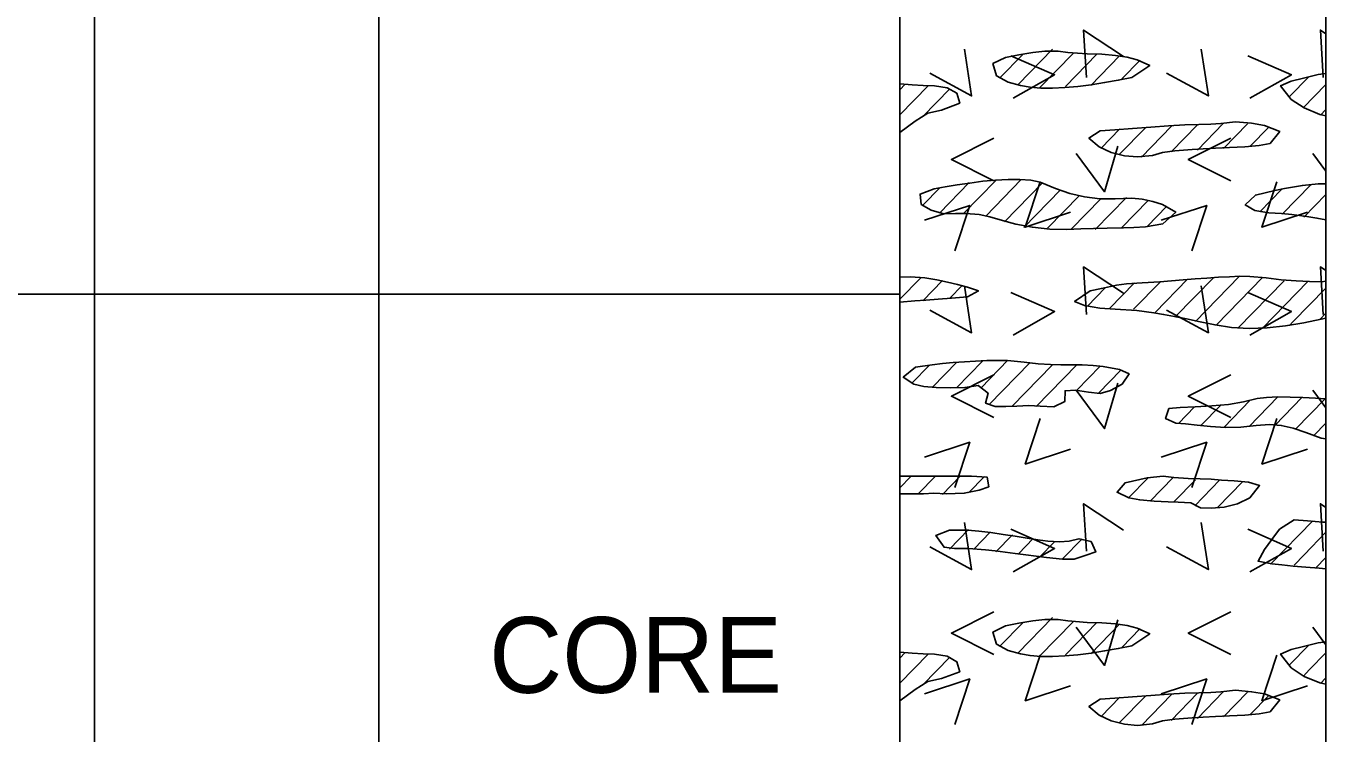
# Model space of a CAD drawing. Extents: x 0 to 0.833, y -0.323 to 0.608.
# Drawn here: x 0.719 to 0.8333, y -0.2609 to -0.1987 of the extents above; entities that cross this region are included whole.
import ezdxf

# ---------------------------------------------------------------- set-up
doc = ezdxf.new("R2010")
doc.units = 0

msp = doc.modelspace()

# ---------------------------------------------------------------- linework, layer by layer
for points in [[(0, -0.32328), (0.83333, -0.32328), (0.83333, 0.60833), (0, 0.60833)], [(0.81233, -0.20113), (0.81063, -0.20101), (0.80977, -0.20088), (0.8086, -0.20087), (0.80755, -0.20101), (0.80632, -0.20121), (0.80513, -0.20145), (0.80403, -0.20198), (0.80436, -0.20304), (0.80536, -0.2036), (0.80647, -0.2039), (0.8073, -0.20405), (0.80824, -0.20413), (0.80926, -0.20414), (0.81035, -0.20409), (0.81149, -0.20398), (0.81267, -0.20384), (0.81386, -0.20365), (0.81506, -0.20344), (0.81625, -0.20321), (0.81783, -0.20213), (0.81673, -0.20163), (0.81585, -0.20142), (0.8148, -0.20127), (0.81361, -0.20116)], [(0.83265, -0.20294), (0.83136, -0.20325), (0.83028, -0.20352), (0.82934, -0.20392), (0.83026, -0.20512), (0.83142, -0.20588), (0.83279, -0.20646), (0.83333, -0.20656), (0.83333, -0.20285)], [(0.79583, -0.20804), (0.79719, -0.20705), (0.79831, -0.20635), (0.79951, -0.20607), (0.80111, -0.20547), (0.80086, -0.20459), (0.80002, -0.20411), (0.79889, -0.20392), (0.79791, -0.20389), (0.79694, -0.20383), (0.79583, -0.20375)], [(0.82537, -0.20709), (0.82408, -0.20724), (0.82319, -0.2073), (0.82214, -0.20732), (0.82091, -0.20736), (0.81947, -0.20745), (0.81792, -0.20757), (0.81632, -0.20769), (0.81475, -0.20779), (0.81348, -0.20789), (0.81247, -0.20853), (0.81337, -0.20929), (0.81444, -0.20979), (0.81561, -0.21008), (0.81675, -0.21019), (0.81807, -0.21007), (0.81896, -0.2098), (0.82003, -0.20965), (0.82157, -0.20953), (0.82253, -0.20947), (0.82362, -0.20942), (0.82483, -0.20935), (0.82618, -0.20929), (0.82745, -0.20918), (0.82842, -0.209), (0.82927, -0.20795), (0.82791, -0.20743), (0.82679, -0.20723)], [(0.79885, -0.213), (0.79763, -0.21346), (0.79773, -0.21436), (0.79859, -0.21488), (0.7997, -0.21518), (0.80074, -0.21517), (0.80165, -0.21515), (0.80281, -0.21524), (0.80377, -0.21545), (0.80486, -0.21579), (0.80606, -0.21609), (0.80751, -0.21637), (0.80905, -0.21655), (0.81052, -0.21658), (0.81177, -0.21652), (0.81289, -0.21648), (0.81408, -0.21645), (0.81553, -0.21641), (0.81642, -0.21638), (0.81745, -0.21635), (0.81897, -0.21608), (0.82011, -0.21504), (0.81896, -0.21437), (0.8181, -0.21411), (0.81717, -0.21391), (0.81626, -0.2138), (0.81479, -0.21386), (0.81343, -0.21386), (0.8121, -0.21371), (0.8108, -0.21341), (0.80953, -0.21295), (0.8082, -0.2124), (0.80736, -0.21224), (0.8064, -0.21216), (0.80536, -0.21216), (0.80427, -0.21222), (0.80314, -0.21233), (0.80201, -0.21248), (0.8009, -0.21264), (0.79984, -0.21282)], [(0.83263, -0.21256), (0.83126, -0.21269), (0.82969, -0.21296), (0.82883, -0.21313), (0.82712, -0.21354), (0.82623, -0.21441), (0.82708, -0.2149), (0.82831, -0.21509), (0.82941, -0.21516), (0.83033, -0.21524), (0.83165, -0.21543), (0.83253, -0.21557), (0.83333, -0.21571), (0.83333, -0.21256)], [(0.82816, -0.22521), (0.82978, -0.22504), (0.83137, -0.22479), (0.8329, -0.22447), (0.83333, -0.22437), (0.83333, -0.22113), (0.83295, -0.22116), (0.83188, -0.22114), (0.83071, -0.22109), (0.82938, -0.22099), (0.82807, -0.22082), (0.82662, -0.2207), (0.82576, -0.22069), (0.82484, -0.22072), (0.82387, -0.22077), (0.82286, -0.22084), (0.82182, -0.22092), (0.82077, -0.221), (0.81973, -0.22109), (0.81872, -0.22116), (0.81715, -0.22126), (0.81579, -0.22135), (0.81491, -0.22148), (0.81357, -0.22176), (0.8126, -0.22197), (0.81121, -0.22289), (0.8121, -0.22325), (0.81345, -0.2235), (0.81479, -0.22359), (0.81668, -0.22369), (0.81818, -0.22389), (0.81905, -0.22404), (0.82, -0.22422), (0.82107, -0.22443), (0.82225, -0.22468), (0.82357, -0.22497), (0.82501, -0.2252), (0.82656, -0.22527)], [(0.79583, -0.22296), (0.79715, -0.22285), (0.79814, -0.22278), (0.79922, -0.2227), (0.80039, -0.22261), (0.80179, -0.22249), (0.80275, -0.22198), (0.80179, -0.22163), (0.80091, -0.22142), (0.80003, -0.2212), (0.79909, -0.22099), (0.79803, -0.22083), (0.79677, -0.22073), (0.79583, -0.22075)], [(0.79708, -0.23019), (0.79794, -0.23037), (0.79904, -0.23048), (0.80028, -0.23051), (0.80156, -0.23046), (0.80274, -0.2303), (0.80361, -0.23097), (0.80338, -0.23186), (0.80422, -0.23213), (0.80517, -0.23215), (0.80613, -0.2321), (0.8072, -0.23206), (0.80818, -0.2321), (0.80939, -0.23217), (0.81037, -0.2317), (0.81038, -0.23076), (0.8113, -0.23069), (0.81244, -0.23088), (0.81346, -0.23099), (0.81438, -0.23073), (0.81539, -0.23019), (0.81601, -0.22928), (0.81517, -0.2289), (0.81374, -0.22863), (0.81285, -0.22853), (0.81187, -0.22848), (0.81, -0.22847), (0.8091, -0.22846), (0.808, -0.22838), (0.80678, -0.22823), (0.8053, -0.2281), (0.80443, -0.22808), (0.80349, -0.2281), (0.80251, -0.22814), (0.80152, -0.2282), (0.80054, -0.22828), (0.79959, -0.22837), (0.7987, -0.22847), (0.79722, -0.22869), (0.79614, -0.22957)], [(0.83241, -0.23141), (0.83129, -0.23134), (0.83017, -0.23131), (0.8291, -0.2313), (0.82811, -0.23134), (0.82728, -0.23143), (0.82608, -0.23173), (0.82476, -0.23196), (0.8233, -0.23209), (0.82183, -0.23218), (0.82051, -0.23224), (0.81951, -0.23233), (0.81922, -0.2332), (0.82013, -0.23362), (0.82097, -0.23367), (0.822, -0.23377), (0.82318, -0.2339), (0.82448, -0.23399), (0.82584, -0.23396), (0.82719, -0.2338), (0.82836, -0.23373), (0.8294, -0.23381), (0.83043, -0.23404), (0.83156, -0.23444), (0.83291, -0.23493), (0.83333, -0.235), (0.83333, -0.23148)], [(0.79583, -0.23982), (0.79676, -0.23983), (0.79792, -0.23981), (0.79882, -0.23977), (0.79992, -0.23982), (0.80151, -0.23977), (0.80282, -0.23951), (0.80367, -0.2392), (0.80354, -0.23836), (0.80216, -0.23827), (0.79583, -0.23827)], [(0.81822, -0.24047), (0.81944, -0.24052), (0.82033, -0.24056), (0.82145, -0.24063), (0.82229, -0.24105), (0.82324, -0.24109), (0.82438, -0.24099), (0.82555, -0.2407), (0.82662, -0.24019), (0.82749, -0.2391), (0.82651, -0.23879), (0.82524, -0.23869), (0.82413, -0.23863), (0.82324, -0.23852), (0.82226, -0.2385), (0.82121, -0.23848), (0.81995, -0.23839), (0.81902, -0.23827), (0.81761, -0.23841), (0.81566, -0.23885), (0.81496, -0.23969), (0.81598, -0.24018), (0.81695, -0.24036)], [(0.83305, -0.24232), (0.83171, -0.24221), (0.83054, -0.24211), (0.82925, -0.24293), (0.82857, -0.24384), (0.82792, -0.24473), (0.82735, -0.24575), (0.82858, -0.24598), (0.82945, -0.24608), (0.83045, -0.24618), (0.83155, -0.24627), (0.83272, -0.24637), (0.83333, -0.24642), (0.83333, -0.24233)], [(0.80066, -0.24462), (0.80188, -0.24463), (0.80339, -0.24476), (0.80423, -0.24485), (0.8051, -0.24496), (0.806, -0.24508), (0.80692, -0.2452), (0.80784, -0.24532), (0.80875, -0.24543), (0.81014, -0.24557), (0.81119, -0.24556), (0.81222, -0.24522), (0.81308, -0.24493), (0.81267, -0.24403), (0.8116, -0.24378), (0.81075, -0.24398), (0.80989, -0.24406), (0.80885, -0.24398), (0.80799, -0.24387), (0.80703, -0.24373), (0.806, -0.24356), (0.80492, -0.2434), (0.80384, -0.24324), (0.8028, -0.24311), (0.80182, -0.24301), (0.8002, -0.24301), (0.79901, -0.24348), (0.79974, -0.24452)], [(0.81233, -0.25113), (0.81063, -0.25101), (0.80977, -0.25088), (0.8086, -0.25087), (0.80755, -0.25101), (0.80632, -0.25121), (0.80513, -0.25145), (0.80403, -0.25198), (0.80436, -0.25304), (0.80536, -0.2536), (0.80647, -0.2539), (0.8073, -0.25405), (0.80824, -0.25413), (0.80926, -0.25414), (0.81035, -0.25409), (0.81149, -0.25398), (0.81267, -0.25384), (0.81386, -0.25365), (0.81506, -0.25344), (0.81625, -0.25321), (0.81783, -0.25213), (0.81673, -0.25163), (0.81585, -0.25142), (0.8148, -0.25127), (0.81361, -0.25116)], [(0.79583, -0.25804), (0.79719, -0.25705), (0.79831, -0.25634), (0.79951, -0.25607), (0.80111, -0.25547), (0.80086, -0.25459), (0.80002, -0.25411), (0.79889, -0.25392), (0.79791, -0.25389), (0.79694, -0.25383), (0.79583, -0.25375)], [(0.83265, -0.25294), (0.83136, -0.25325), (0.83028, -0.25352), (0.82934, -0.25392), (0.83026, -0.25512), (0.83142, -0.25588), (0.83279, -0.25646), (0.83333, -0.25656), (0.83333, -0.25285)], [(0.82537, -0.25709), (0.82408, -0.25724), (0.82319, -0.2573), (0.82214, -0.25732), (0.82091, -0.25736), (0.81947, -0.25745), (0.81792, -0.25757), (0.81632, -0.25769), (0.81475, -0.25779), (0.81348, -0.25789), (0.81247, -0.25853), (0.81337, -0.25929), (0.81444, -0.25979), (0.81561, -0.26008), (0.81675, -0.26019), (0.81807, -0.26007), (0.81896, -0.2598), (0.82003, -0.25965), (0.82157, -0.25953), (0.82253, -0.25947), (0.82362, -0.25942), (0.82483, -0.25935), (0.82618, -0.25929), (0.82745, -0.25918), (0.82842, -0.259), (0.82927, -0.25795), (0.82791, -0.25743), (0.82679, -0.25723)]]:
    msp.add_lwpolyline(points, close=True)
for points in [[(0.725, 0.55417), (0.725, -0.28575)], [(0.75, 0.55417), (0.75, -0.28575)], [(0.75, 0.55417), (0.75, -0.28575)], [(0.79583, 0.55417), (0.79583, -0.28575)], [(0.725, 0.54167), (0.725, -0.28575)], [(0.83333, -0.28575), (0.83333, 0.50165)], [(0.81551, -0.20134), (0.81201, -0.19903), (0.81226, -0.20321)], [(0.83333, -0.19935), (0.83284, -0.19903), (0.83309, -0.20321)], [(0.79847, -0.20282), (0.80215, -0.20482), (0.80153, -0.2007)], [(0.80465, -0.20324), (0.80667, -0.20117)], [(0.80626, -0.20381), (0.80928, -0.20071)], [(0.80809, -0.20414), (0.81111, -0.20105)], [(0.81041, -0.20398), (0.81318, -0.20115)], [(0.8193, -0.20282), (0.82299, -0.20482), (0.82236, -0.2007)], [(0.80562, -0.20128), (0.80946, -0.20296), (0.80581, -0.20502)], [(0.81264, -0.2039), (0.81518, -0.2013)], [(0.81536, -0.20333), (0.81699, -0.20167)], [(0.82645, -0.20128), (0.83029, -0.20296), (0.82664, -0.20502)], [(0.8301, -0.20491), (0.83184, -0.20312)], [(0.7963, -0.20379), (0.79583, -0.20427)], [(0.79834, -0.20392), (0.79583, -0.20649)], [(0.79786, -0.20662), (0.80023, -0.20419)], [(0.83131, -0.20588), (0.83333, -0.20381)], [(0.83285, -0.20651), (0.83333, -0.20602)], [(0.81519, -0.20772), (0.81354, -0.20942)], [(0.81514, -0.20998), (0.81748, -0.20759)], [(0.81709, -0.2102), (0.81974, -0.20749)], [(0.8197, -0.20975), (0.82203, -0.20735)], [(0.82202, -0.20958), (0.8243, -0.20725)], [(0.82431, -0.20945), (0.82644, -0.20726)], [(0.82663, -0.20928), (0.82834, -0.20753)], [(0.80412, -0.20853), (0.80038, -0.21041), (0.80412, -0.21228)], [(0.81134, -0.20988), (0.81384, -0.21325), (0.81503, -0.20925)], [(0.82496, -0.20853), (0.82121, -0.21041), (0.82496, -0.21228)], [(0.83217, -0.20988), (0.83333, -0.21144)], [(0, -0.21078), (0, -0.32328), (0.83333, -0.32328), (0.83333, -0.21078)], [(0.79933, -0.21513), (0.80195, -0.21244)], [(0.80142, -0.2152), (0.8043, -0.21225)], [(0.80653, -0.21217), (0.8034, -0.21539)], [(0.80506, -0.21589), (0.8084, -0.21247)], [(0.80818, -0.21237), (0.80687, -0.21637), (0.81087, -0.21505)], [(0.82901, -0.21237), (0.8277, -0.21637), (0.8317, -0.21505)], [(0.83203, -0.21261), (0.82949, -0.21521)], [(0.79938, -0.21287), (0.79786, -0.21442)], [(0.80997, -0.21307), (0.80675, -0.21638)], [(0.81164, -0.21358), (0.80884, -0.21644)], [(0.81303, -0.21658), (0.81579, -0.21375)], [(0.82751, -0.21502), (0.82945, -0.21303)], [(0.83138, -0.21548), (0.83333, -0.21348)], [(0.80069, -0.21845), (0.802, -0.21445), (0.798, -0.21576)], [(0.81353, -0.21386), (0.81094, -0.21651)], [(0.81534, -0.21642), (0.81768, -0.21402)], [(0.8176, -0.21632), (0.81934, -0.21453)], [(0.82152, -0.21845), (0.82284, -0.21445), (0.81884, -0.21576)], [(0.83333, -0.2157), (0.83333, -0.21569)], [(0.81551, -0.22217), (0.81201, -0.21986), (0.81226, -0.22405)], [(0.82569, -0.2207), (0.82184, -0.22465)], [(0.83333, -0.22018), (0.83284, -0.21986), (0.83309, -0.22405)], [(0.79765, -0.22085), (0.79583, -0.22271)], [(0.7996, -0.22106), (0.79786, -0.22284)], [(0.79847, -0.22366), (0.80215, -0.22566), (0.80153, -0.22153)], [(0.8013, -0.22154), (0.80027, -0.22259)], [(0.81392, -0.2217), (0.81235, -0.22331)], [(0.8143, -0.22352), (0.8165, -0.22127)], [(0.8164, -0.22359), (0.81879, -0.22114)], [(0.81829, -0.22387), (0.82114, -0.22094)], [(0.8193, -0.22366), (0.82299, -0.22566), (0.82236, -0.22153)], [(0.82004, -0.22429), (0.82346, -0.22078)], [(0.82775, -0.2208), (0.8237, -0.22495)], [(0.82964, -0.22108), (0.82557, -0.22526)], [(0.83173, -0.22115), (0.82774, -0.22524)], [(0.83333, -0.22173), (0.83042, -0.2247), (0.83012, -0.22502)], [(0.70417, -0.22225), (0.725, -0.22225)], [(0.725, -0.22225), (0.75, -0.22225)], [(0.75, -0.22225), (0.79583, -0.22225)], [(0.80562, -0.22211), (0.80946, -0.22379), (0.80581, -0.22586)], [(0.82645, -0.22211), (0.83029, -0.22379), (0.82664, -0.22586)], [(0.83281, -0.22447), (0.83333, -0.22394)], [(0.79844, -0.22851), (0.79691, -0.23008)], [(0.79871, -0.23045), (0.80085, -0.22825)], [(0.80083, -0.23049), (0.80311, -0.22815)], [(0.80534, -0.22807), (0.80299, -0.23049)], [(0.80367, -0.232), (0.80732, -0.22826)], [(0.80571, -0.23212), (0.80924, -0.22851)], [(0.81142, -0.22849), (0.80785, -0.23214)], [(0.81141, -0.23071), (0.81348, -0.22859)], [(0.80412, -0.22937), (0.80038, -0.23124), (0.80412, -0.23312)], [(0.81528, -0.22895), (0.81331, -0.23097)], [(0.82496, -0.22937), (0.82121, -0.23124), (0.82496, -0.23312)], [(0.81134, -0.23071), (0.81384, -0.23408), (0.81503, -0.23008)], [(0.83217, -0.23071), (0.83333, -0.23227)], [(0.82233, -0.23381), (0.82408, -0.23202)], [(0.82433, -0.23398), (0.82666, -0.23159)], [(0.82909, -0.2313), (0.82656, -0.2339)], [(0.82885, -0.23377), (0.83122, -0.23134)], [(0.83325, -0.23148), (0.83065, -0.23413)], [(0.80818, -0.2332), (0.80687, -0.2372), (0.81087, -0.23589)], [(0.82035, -0.23363), (0.82176, -0.23218)], [(0.82901, -0.2332), (0.8277, -0.2372), (0.8317, -0.23589)], [(0.83333, -0.2336), (0.83227, -0.23469)], [(0.80069, -0.23928), (0.802, -0.23528), (0.798, -0.23659)], [(0.82152, -0.23928), (0.82284, -0.23528), (0.81884, -0.23659)], [(0.79583, -0.2393), (0.79681, -0.2383)], [(0.79898, -0.23828), (0.79747, -0.23983)], [(0.80116, -0.23827), (0.79959, -0.23987)], [(0.80328, -0.23831), (0.80188, -0.23974)], [(0.8177, -0.23841), (0.81596, -0.24019)], [(0.81988, -0.23839), (0.81785, -0.24047)], [(0.82185, -0.23858), (0.81997, -0.24051)], [(0.824, -0.23859), (0.82178, -0.24087)], [(0.82601, -0.23875), (0.82378, -0.24103)], [(0.81551, -0.24301), (0.81201, -0.24069), (0.81226, -0.24488)], [(0.83333, -0.24102), (0.83284, -0.24069), (0.83309, -0.24488)], [(0.79847, -0.24449), (0.80215, -0.24649), (0.80153, -0.24236)], [(0.8193, -0.24449), (0.82299, -0.24649), (0.82236, -0.24236)], [(0.83217, -0.24219), (0.82844, -0.24601)], [(0.80188, -0.24297), (0.8002, -0.24469)], [(0.8038, -0.24321), (0.80237, -0.24467)], [(0.80575, -0.24343), (0.80429, -0.24492)], [(0.80562, -0.24294), (0.80946, -0.24463), (0.80581, -0.24669)], [(0.82645, -0.24294), (0.83029, -0.24463), (0.82664, -0.24669)], [(0.83333, -0.24321), (0.8314, -0.24519), (0.83052, -0.24609)], [(0.80758, -0.24376), (0.80627, -0.24511)], [(0.80941, -0.24409), (0.80816, -0.24538)], [(0.81188, -0.24378), (0.81016, -0.24554)], [(0.83333, -0.24543), (0.83245, -0.24633)], [(0.80412, -0.2502), (0.80038, -0.25208), (0.80412, -0.25395)], [(0.82496, -0.2502), (0.82121, -0.25208), (0.82496, -0.25395)], [(0.80465, -0.25324), (0.80667, -0.25117)], [(0.80626, -0.25381), (0.80928, -0.25071)], [(0.80809, -0.25414), (0.81111, -0.25105)], [(0.81041, -0.25398), (0.81318, -0.25115)], [(0.81134, -0.25154), (0.81384, -0.25492), (0.81503, -0.25092)], [(0.81264, -0.2539), (0.81518, -0.2513)], [(0.83217, -0.25154), (0.83333, -0.2531)], [(0.81536, -0.25333), (0.81699, -0.25167)], [(0.7963, -0.25379), (0.79583, -0.25427)], [(0.8301, -0.25491), (0.83184, -0.25312)], [(0.83131, -0.25588), (0.83188, -0.25529), (0.83333, -0.25381)], [(0.79834, -0.25392), (0.79583, -0.25649)], [(0.79786, -0.25662), (0.80023, -0.25419)], [(0.80818, -0.25403), (0.80687, -0.25803), (0.81087, -0.25672)], [(0.82901, -0.25403), (0.8277, -0.25803), (0.8317, -0.25672)], [(0.80069, -0.26011), (0.802, -0.25611), (0.798, -0.25743)], [(0.82152, -0.26011), (0.82284, -0.25611), (0.81884, -0.25743)], [(0.83285, -0.25651), (0.83333, -0.25602)], [(0.82202, -0.25958), (0.8243, -0.25725)], [(0.82431, -0.25945), (0.82644, -0.25726)], [(0.81519, -0.25772), (0.81354, -0.25942)], [(0.81514, -0.25998), (0.81748, -0.25759)], [(0.81709, -0.2602), (0.81974, -0.25749)], [(0.8197, -0.25975), (0.82203, -0.25735)], [(0.82663, -0.25928), (0.82834, -0.25753)]]:
    msp.add_lwpolyline(points)

# ---------------------------------------------------------------- texts
msp.add_text('CORE', height=0.006667).set_placement((0.75971, -0.25733))

doc.saveas('drawing.dxf')
